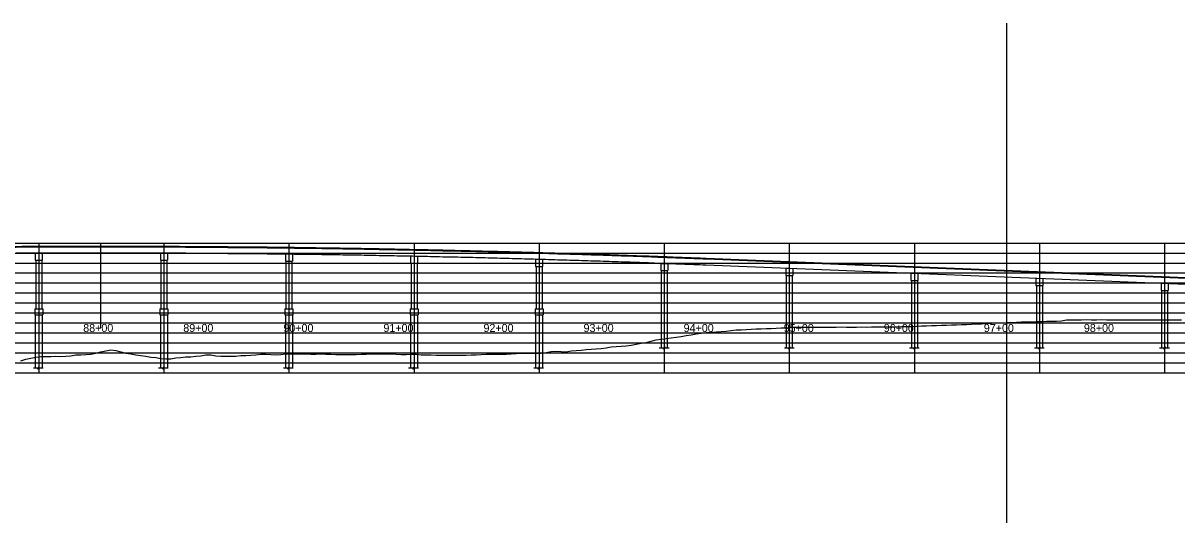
# Model space of a CAD drawing. Extents: x -464 to 4306, y -1372 to 300.
# Drawn here: x 1952 to 3105, y -200 to 300 of the extents above; entities that cross this region are included whole.
import ezdxf

# ---------------------------------------------------------------- set-up
doc = ezdxf.new("R2010")
doc.units = 0
for name, color, linetype in [('BR_AUTO DIMENSION', 7, 'Continuous'), ('BR_GRID LINES', 7, 'Continuous'), ('Default', 7, 'Continuous'), ('Mis Ground Lines', 7, 'Continuous'), ('NOPLOT', 7, 'Continuous'), ('sub interior bent cap lines', 7, 'Continuous'), ('Sup Concrete Girder Lines', 7, 'Continuous'), ('Sup Concrete Slab Lines', 7, 'Continuous')]:
    doc.layers.add(name, color=color, linetype=linetype)

msp = doc.modelspace()

# ---------------------------------------------------------------- linework, layer by layer
at = {"layer": 'BR_AUTO DIMENSION'}
for points in [[(2587.8, -25), (2592.1, -25), (2592.1, -26.1), (2593.2, -23.9), (2593.2, -25), (2597.5, -25)], [(2712.8, -25), (2717.1, -25), (2717.1, -26.1), (2718.2, -23.9), (2718.2, -25), (2722.5, -25)], [(2837.8, -25), (2842.1, -25), (2842.1, -26.1), (2843.2, -23.9), (2843.2, -25), (2847.5, -25)], [(2962.8, -25), (2967.1, -25), (2967.1, -26.1), (2968.2, -23.9), (2968.2, -25), (2972.5, -25)], [(3087.8, -25), (3092.1, -25), (3092.1, -26.1), (3093.2, -23.9), (3093.2, -25), (3097.5, -25)], [(1962.3, -45), (1966.6, -45), (1966.6, -46.1), (1967.7, -43.9), (1967.7, -45), (1972, -45)], [(2087.3, -45), (2091.6, -45), (2091.6, -46.1), (2092.7, -43.9), (2092.7, -45), (2097, -45)], [(2212.3, -45), (2216.6, -45), (2216.6, -46.1), (2217.7, -43.9), (2217.7, -45), (2222, -45)], [(2337.3, -45), (2341.6, -45), (2341.6, -46.1), (2342.7, -43.9), (2342.7, -45), (2347, -45)], [(2462.3, -45), (2466.6, -45), (2466.6, -46.1), (2467.7, -43.9), (2467.7, -45), (2472, -45)]]:
    msp.add_lwpolyline(points, dxfattribs=at)
at = {"layer": 'BR_GRID LINES'}
for p, q in [((2934.7, 300), (2934.7, -200)), ((-80.3, 80), (3939.7, 80)), ((-80.3, 70), (3939.7, 70)), ((-80.3, 60), (3939.7, 60)), ((-80.3, 50), (3939.7, 50)), ((-80.3, 40), (3939.7, 40)), ((-80.3, 30), (3939.7, 30)), ((-80.3, 20), (3939.7, 20)), ((-80.3, 10), (3939.7, 10)), ((-80.3, 0), (3939.7, 0)), ((-80.3, -10), (3939.7, -10)), ((-80.3, -20), (3939.7, -20)), ((-80.3, -30), (3939.7, -30)), ((-80.3, -40), (3939.7, -40)), ((-80.3, -50), (3939.7, -50))]:
    msp.add_line(p, q, dxfattribs=at)
at = {"layer": 'Default'}
for p, q in [((1967.7, 80), (1967.7, -50)), ((2029.7, -5), (2029.7, 80)), ((2092.7, 80), (2092.7, -50)), ((2217.7, 80), (2217.7, -50)), ((2342.7, 80), (2342.7, -50)), ((2467.7, 80), (2467.7, -50)), ((2592.7, 80), (2592.7, -50)), ((2717.7, 80), (2717.7, -50)), ((2842.7, 80), (2842.7, -50)), ((2967.7, 80), (2967.7, -50)), ((3092.7, 80), (3092.7, -50)), ((-170.3, 0), (4029.7, 0))]:
    msp.add_line(p, q, dxfattribs=at)
at = {"layer": 'Mis Ground Lines'}
for points in [[(2729.7, -4.3), (2734.7, -4.2), (2739.7, -4.3), (2744.7, -4.2), (2749.7, -4.2), (2754.7, -4.2), (2759.7, -4.1), (2764.7, -4.1), (2769.7, -4), (2774.7, -4.1), (2779.7, -4.1), (2784.7, -4.1), (2789.7, -3.9), (2794.7, -4.1), (2799.7, -3.9), (2804.7, -3.9), (2809.7, -3.8), (2814.7, -3.8), (2819.7, -3.8), (2824.7, -3.7), (2829.7, -3.6), (2834.7, -3.5), (2839.7, -3.4), (2844.7, -3.2), (2849.7, -3), (2854.7, -2.9), (2859.7, -2.6), (2864.7, -2.4), (2869.7, -2.3), (2874.7, -2.1), (2879.7, -1.9), (2884.7, -1.8), (2889.7, -1.6), (2894.7, -1.5), (2899.7, -1.3), (2904.7, -1), (2909.7, -1), (2914.7, -0.6), (2919.7, -0.3), (2924.7, 0), (2929.7, 0.2), (2934.7, 0.4), (2939.7, 0.6), (2944.7, 0.8), (2949.7, 1), (2954.7, 1.2), (2959.7, 1.3), (2964.7, 1.4), (2969.7, 1.6), (2974.7, 1.7), (2979.7, 1.8), (2984.7, 1.9), (2989.7, 2), (2994.7, 3.2), (2999.7, 3.3), (3004.7, 3.2), (3009.7, 3.2), (3014.7, 3.4), (3019.7, 3.3), (3024.7, 3.3), (3029.7, 3.4), (3034.7, 3.2), (3039.7, 3.1), (3044.7, 3), (3049.7, 3.1), (3054.7, 3.1), (3059.7, 3.1), (3064.7, 3.1), (3069.7, 3.1), (3074.7, 3.1), (3079.7, 3.1), (3084.7, 3.2), (3089.7, 3.1), (3094.7, 3.1), (3099.7, 3.1), (3104.7, 3), (3109.7, 3)], [(2229.7, -30.8), (2234.7, -30.8), (2239.7, -31.1), (2244.7, -31.3), (2249.7, -31), (2254.7, -31.1), (2259.7, -31.3), (2264.7, -31.4), (2269.7, -31.4), (2274.7, -31.4), (2279.7, -31.4), (2284.7, -31.4), (2289.7, -31.3), (2294.7, -31.1), (2299.7, -30.7), (2304.7, -30.7), (2309.7, -30.9), (2314.7, -30.9), (2319.7, -31), (2324.7, -31.3), (2329.7, -31.4), (2334.7, -31.4), (2339.7, -31.2), (2344.7, -31.3), (2349.7, -31.7), (2354.7, -31.7), (2359.7, -32), (2364.7, -32.1), (2369.7, -32.2), (2374.7, -32.1), (2379.7, -32.2), (2384.7, -32.1), (2389.7, -32.1), (2394.7, -32.1), (2399.7, -32), (2404.7, -31.8), (2409.7, -31.5), (2414.7, -31.2), (2419.7, -31.1), (2424.7, -31.2), (2429.7, -31.2), (2434.7, -31.1), (2439.7, -30.8), (2444.7, -30.6), (2449.7, -30.3), (2454.7, -30.3), (2459.7, -30.3), (2464.7, -30.4), (2469.7, -30.1), (2474.7, -29.5), (2479.7, -28.5), (2484.7, -28.1), (2489.7, -28.5), (2494.7, -28.7), (2499.7, -27.8), (2504.7, -27.6), (2509.7, -27.1), (2514.7, -26.6), (2519.7, -26.3), (2524.7, -25.7), (2529.7, -25.4), (2534.7, -24.7), (2539.7, -24), (2544.7, -23.4), (2549.7, -23.3), (2554.7, -22.8), (2559.7, -22.2), (2564.7, -21.2), (2569.7, -20.3), (2574.7, -19.6), (2579.7, -18.2), (2584.7, -17), (2589.7, -16.2), (2594.7, -15.4), (2599.7, -14.7), (2604.7, -14.2), (2609.7, -13.5), (2614.7, -12.6), (2619.7, -11.7), (2624.7, -10.8), (2629.7, -10.1), (2634.7, -9.5), (2639.7, -9.2), (2644.7, -8.9), (2649.7, -8.6), (2654.7, -8.1), (2659.7, -7.5), (2664.7, -7), (2669.7, -6.7), (2674.7, -6.4), (2679.7, -6.1), (2684.7, -5.8), (2689.7, -5.7), (2694.7, -5.6), (2699.7, -5.4), (2704.7, -5.1), (2709.7, -4.9), (2714.7, -4.7), (2719.7, -4.3), (2724.7, -4.3), (2729.7, -4.3)], [(1949.7, -37.9), (1954.7, -36.3), (1959.7, -35.2), (1964.7, -34.1), (1969.7, -33.6), (1974.7, -33.6), (1979.7, -33.4), (1984.7, -33.3), (1989.7, -33.4), (1994.7, -33.2), (1999.7, -32.8), (2004.7, -32), (2009.7, -31.8), (2014.7, -31.6), (2019.7, -31.2), (2024.7, -30.1), (2029.7, -28.9), (2034.7, -27.9), (2039.7, -26.8), (2044.7, -27.4), (2049.7, -28.9), (2054.7, -30.2), (2059.7, -31), (2064.7, -31.8), (2069.7, -32.6), (2074.7, -33.3), (2079.7, -34.1), (2084.7, -34.6), (2089.7, -35.5), (2094.7, -36), (2099.7, -35.7), (2104.7, -34.9), (2109.7, -34.4), (2114.7, -34), (2119.7, -33.7), (2124.7, -33.3), (2129.7, -32.7), (2134.7, -31.7), (2139.7, -31.8), (2144.7, -32.8), (2149.7, -33.2), (2154.7, -33.1), (2159.7, -33.2), (2164.7, -33.2), (2169.7, -32.6), (2174.7, -32.5), (2179.7, -32.3), (2184.7, -31.9), (2189.7, -31.2), (2194.7, -31.1), (2199.7, -31.5), (2204.7, -31.8), (2209.7, -31.4), (2214.7, -31), (2219.7, -31), (2224.7, -30.9), (2229.7, -30.8)]]:
    msp.add_lwpolyline(points, dxfattribs=at)
at = {"layer": 'sub interior bent cap lines'}
for p, q in [((1964.2, 69.8), (1964.2, 62.8)), ((1971.2, 69.8), (1964.2, 69.8)), ((1971.2, 69.8), (1971.2, 62.8)), ((2089.2, 69.8), (2089.2, 62.8)), ((2096.2, 69.8), (2089.2, 69.8)), ((2096.2, 69.8), (2096.2, 62.8)), ((1964.2, 62.8), (1971.2, 62.8)), ((1964.7, 62.8), (1964.7, 14)), ((1970.7, 62.8), (1970.7, 14)), ((2089.2, 62.8), (2096.2, 62.8)), ((2089.7, 62.8), (2089.7, 14)), ((2095.7, 62.8), (2095.7, 14)), ((2214.2, 68.8), (2214.2, 61.7)), ((2221.2, 68.7), (2214.2, 68.8)), ((2214.2, 61.7), (2221.2, 61.7)), ((2214.7, 61.7), (2214.7, 14)), ((2220.7, 61.7), (2220.7, 14)), ((2221.2, 68.7), (2221.2, 61.7)), ((2339.2, 66.7), (2339.2, 59.7)), ((2346.2, 66.6), (2339.2, 66.7)), ((2339.2, 59.7), (2346.2, 59.7)), ((2339.7, 59.7), (2339.7, 14)), ((2345.7, 59.7), (2345.7, 14)), ((2346.2, 66.6), (2346.2, 59.7)), ((2464.2, 63.7), (2464.2, 56.6)), ((2471.2, 63.5), (2464.2, 63.7)), ((2471.2, 63.5), (2471.2, 56.6)), ((2589.2, 59.5), (2589.2, 52.4)), ((2589.2, 59.5), (2596.2, 59.3)), ((2596.2, 59.3), (2596.2, 52.4)), ((2464.2, 56.6), (2471.2, 56.6)), ((2464.7, 56.6), (2464.7, 14)), ((2470.7, 56.6), (2470.7, 14)), ((2589.2, 52.4), (2596.2, 52.4)), ((2589.7, 52.4), (2589.7, -25)), ((2595.7, 52.4), (2595.7, -25)), ((2714.2, 54.6), (2714.2, 47.5)), ((2721.2, 54.3), (2714.2, 54.6)), ((2714.2, 47.5), (2721.2, 47.5)), ((2714.7, 47.5), (2714.7, -25)), ((2720.7, 47.5), (2720.7, -25)), ((2721.2, 54.3), (2721.2, 47.5)), ((2839.2, 49.6), (2839.2, 42.5)), ((2846.2, 49.3), (2839.2, 49.6)), ((2846.2, 49.3), (2846.2, 42.5)), ((2839.2, 42.5), (2846.2, 42.5)), ((2839.7, 42.5), (2839.7, -25)), ((2845.7, 42.5), (2845.7, -25)), ((2964.2, 44.6), (2964.2, 37.5)), ((2971.2, 44.3), (2964.2, 44.6)), ((2964.2, 37.5), (2971.2, 37.5)), ((2964.7, 37.5), (2964.7, -25)), ((2970.7, 37.5), (2970.7, -25)), ((2971.2, 44.3), (2971.2, 37.5)), ((3089.2, 39.6), (3089.2, 32.5)), ((3096.2, 39.3), (3089.2, 39.6)), ((3096.2, 39.3), (3096.2, 32.5)), ((3089.2, 32.5), (3096.2, 32.5)), ((3089.7, 32.5), (3089.7, -25)), ((3095.7, 32.5), (3095.7, -25)), ((1963.7, 14), (1971.7, 14)), ((1963.7, 14), (1963.7, 8)), ((1971.7, 14), (1971.7, 8)), ((2088.7, 14), (2096.7, 14)), ((2088.7, 14), (2088.7, 8)), ((2096.7, 14), (2096.7, 8)), ((2213.7, 14), (2221.7, 14)), ((2213.7, 14), (2213.7, 8)), ((2221.7, 14), (2221.7, 8)), ((2338.7, 14), (2346.7, 14)), ((2338.7, 14), (2338.7, 8)), ((2346.7, 14), (2346.7, 8)), ((2463.7, 14), (2471.7, 14)), ((2463.7, 14), (2463.7, 8)), ((2471.7, 14), (2471.7, 8)), ((1963.7, 8), (1971.7, 8)), ((1964.2, 8), (1964.2, -45)), ((1971.2, 8), (1971.2, -45)), ((2088.7, 8), (2096.7, 8)), ((2089.2, 8), (2089.2, -45)), ((2096.2, 8), (2096.2, -45)), ((2213.7, 8), (2221.7, 8)), ((2214.2, 8), (2214.2, -45)), ((2221.2, 8), (2221.2, -45)), ((2338.7, 8), (2346.7, 8)), ((2339.2, 8), (2339.2, -45)), ((2346.2, 8), (2346.2, -45)), ((2463.7, 8), (2471.7, 8)), ((2464.2, 8), (2464.2, -45)), ((2471.2, 8), (2471.2, -45))]:
    msp.add_line(p, q, dxfattribs=at)
at = {"layer": 'Sup Concrete Girder Lines'}
for p, q in [((2634.4, 58.1), (3584.4, 20.1)), ((2634.6, 64.1), (3584.6, 26.1))]:
    msp.add_line(p, q, dxfattribs=at)
for points in [[(1424.7, 64.1), (1448.9, 65.1), (1473.1, 66), (1497.3, 66.9), (1521.5, 67.7), (1545.7, 68.5), (1569.9, 69.2), (1594.1, 70), (1618.3, 70.6), (1642.5, 71.3), (1666.7, 71.9), (1690.9, 72.4), (1715.1, 73), (1739.3, 73.4), (1763.5, 73.9), (1787.7, 74.3), (1811.9, 74.7), (1836.1, 75), (1860.3, 75.3), (1884.5, 75.5), (1908.7, 75.7), (1932.9, 75.9), (1957.1, 76.1), (1981.3, 76.2), (2005.5, 76.2), (2029.7, 76.2), (2053.9, 76.2), (2078.1, 76.2), (2102.3, 76.1), (2126.5, 75.9), (2150.7, 75.7), (2174.9, 75.5), (2199.1, 75.3), (2223.3, 75), (2247.5, 74.7), (2271.7, 74.3), (2295.9, 73.9), (2320.1, 73.4), (2344.3, 73), (2368.5, 72.4), (2392.7, 71.9), (2416.9, 71.3), (2441.1, 70.6), (2465.3, 70), (2489.5, 69.2), (2513.7, 68.5), (2537.8, 67.7), (2562, 66.9), (2586.2, 66), (2610.4, 65.1), (2634.6, 64.1)], [(1424.9, 58.1), (1449.1, 59.1), (1473.3, 60), (1497.5, 60.9), (1521.7, 61.7), (1545.9, 62.5), (1570.1, 63.2), (1594.3, 64), (1618.5, 64.6), (1642.6, 65.3), (1666.8, 65.9), (1691, 66.4), (1715.2, 67), (1739.4, 67.4), (1763.6, 67.9), (1787.8, 68.3), (1812, 68.7), (1836.2, 69), (1860.3, 69.3), (1884.5, 69.5), (1908.7, 69.7), (1932.9, 69.9), (1957.1, 70.1), (1981.3, 70.2), (2005.5, 70.2), (2029.7, 70.2), (2053.9, 70.2), (2078.1, 70.2), (2102.2, 70.1), (2126.4, 69.9), (2150.6, 69.7), (2174.8, 69.5), (2199, 69.3), (2223.2, 69), (2247.4, 68.7), (2271.6, 68.3), (2295.8, 67.9), (2319.9, 67.4), (2344.1, 67), (2368.3, 66.4), (2392.5, 65.9), (2416.7, 65.3), (2440.9, 64.6), (2465.1, 64), (2489.3, 63.2), (2513.5, 62.5), (2537.6, 61.7), (2561.8, 60.9), (2586, 60), (2610.2, 59.1), (2634.4, 58.1)]]:
    msp.add_spline(points, degree=3, dxfattribs=at)
at = {"layer": 'Sup Concrete Slab Lines'}
msp.add_line((2634.7, 64.8), (3584.7, 26.8), dxfattribs=at)
msp.add_spline([(1424.7, 64.8), (1448.9, 65.7), (1473.1, 66.7), (1497.3, 67.5), (1521.5, 68.4), (1545.7, 69.2), (1569.9, 69.9), (1594.1, 70.6), (1618.3, 71.3), (1642.5, 71.9), (1666.7, 72.5), (1690.9, 73.1), (1715.1, 73.6), (1739.3, 74.1), (1763.5, 74.6), (1787.7, 75), (1811.9, 75.3), (1836.1, 75.7), (1860.3, 76), (1884.5, 76.2), (1908.7, 76.4), (1932.9, 76.6), (1957.1, 76.7), (1981.3, 76.8), (2005.5, 76.9), (2029.7, 76.9), (2053.9, 76.9), (2078.1, 76.8), (2102.3, 76.7), (2126.5, 76.6), (2150.7, 76.4), (2174.9, 76.2), (2199.1, 76), (2223.3, 75.7), (2247.5, 75.3), (2271.7, 75), (2295.9, 74.6), (2320.1, 74.1), (2344.3, 73.6), (2368.5, 73.1), (2392.7, 72.5), (2416.9, 71.9), (2441.1, 71.3), (2465.3, 70.6), (2489.5, 69.9), (2513.7, 69.2), (2537.9, 68.4), (2562.1, 67.5), (2586.3, 66.7), (2610.5, 65.7), (2634.7, 64.8)], degree=3, dxfattribs=at)

# ---------------------------------------------------------------- texts
at = {"layer": 'NOPLOT'}
for s, p in [('88+00', (2012.1, -9)), ('89+00', (2112.1, -9)), ('90+00', (2212.1, -9)), ('91+00', (2312.1, -9)), ('92+00', (2412.1, -9)), ('93+00', (2512.1, -9)), ('94+00', (2612.1, -9)), ('95+00', (2712.1, -9)), ('96+00', (2812.1, -9)), ('97+00', (2912.1, -9)), ('98+00', (3012.1, -9))]:
    msp.add_text(s, height=8, dxfattribs=at).set_placement(p)

doc.saveas('drawing.dxf')
